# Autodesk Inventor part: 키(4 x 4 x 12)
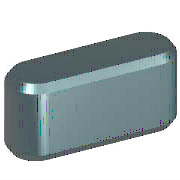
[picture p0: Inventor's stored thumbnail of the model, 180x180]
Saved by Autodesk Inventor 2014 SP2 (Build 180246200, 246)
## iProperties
IsCustomPart: 0
Created: 2009-02
Part Number: 키(4 x 4 x 12)
Material: 강철, 연강
Description: 키 및 해당 키홈
Document SubType Name: Modeling
Standard: KS B 1311
Designer: KYOUNG IL JANG
Standards Organization: KS
Language: ko-KR
Size Designation: 4 x 4 x 12
Categories: <MemberInstance><Categories><Category DisplayName="샤프트 부품" InternalName="7f7aeb1f-a693-4053-b835-cee3144e0d98" Mnemonic="SHFT"><Category DisplayName="키" Interna
Density: 7.86 g/cm^3
Mass: 1.38739 g
Surface Area: 1.94869 cm^2
Volume: 0.176513 cm^3
Appearance: 강철
Author: KYOUNG IL JANG
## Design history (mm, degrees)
workplane "Work Plane1"
workplane "Work Plane2"
sketch "스케치1"
  geometry: L1 (2, 2)-(10, 2); L2 (10, -2)-(2, -2); L3 (0, 9.4)-(0, -7.4) reference; L4 (-5, 0)-(30, 0) reference; L5 (12, 0)-(12, 7); A1 r 2 centre (2, 0) between (2, 2) and (2, -2); A2 r 2 centre (10, 0) between (10, -2) and (10, 2)
  constraints: 6 end point, 5 point on circle, 4 tangent, 3 point on line, 2 centre point, 1 horizontal, 1 parallel, 1 perpendicular
  dimensions: "d0" = 2 radius of A1 (= 0.5 x PB); "d13" = 2 radius of A2 (= 0.5 x PB); "d14" = 12 distance between parallel lines of L5 L3 (= NLG)
extrude "본체1" new body sketch "스케치1" taper "d3" = 0 deg; stored distance "d4" = 10
workplane "Work Plane3"
body "Solid1"
chamfer "모따기1" distance "d8" = 0.25 (= PHH); stored, may be unused: second distance "d9" = 0.25 (= PHH), angle "d15" = 45 deg
other parameters: "d1" = -2.5 (= -PNT), "d2" = 1.5 (= PH - PNT), "NLG" = 12 [user parameter; used in 3 equation terms], "PB" = 4 [user parameter; used in 2 equation terms], "PNT" = 2.5 [user parameter; used in 2 equation terms], "PH" = 4 [user parameter; used in 1 equation term], "PHH" = 0.25 [user parameter; used in 2 equation terms], "d10" = 0, "d16" = 0, "d17" = 0, "d18" = 0, "PLB2" = 12 (= NLG) [user parameter], "WDMAX" = 12 [user parameter], "PLB1" = 12 (= NLG) [user parameter], "RR" = 0.08 [user parameter], "PUEB" = 1.8 [user parameter]
